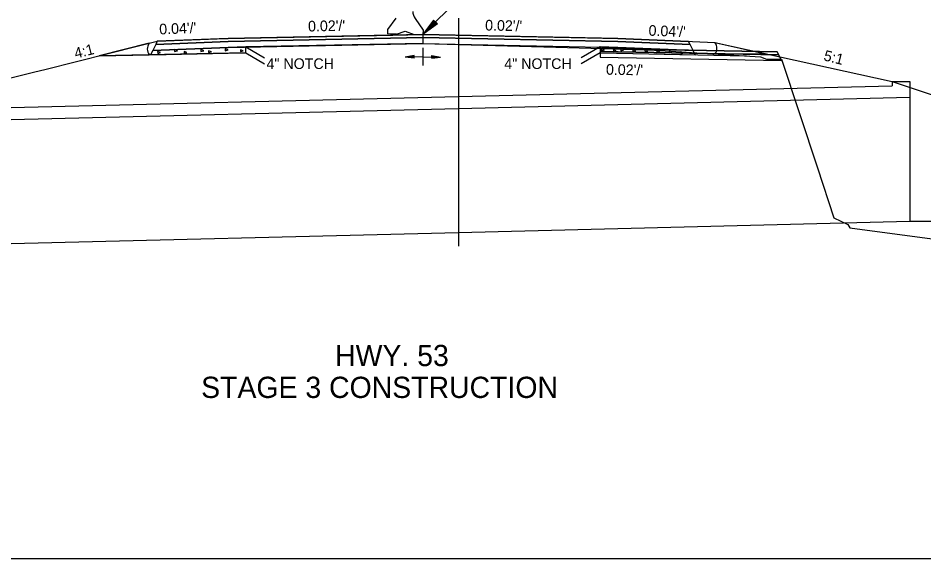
# Model space of a CAD drawing. Extents: x 2829243 to 2838161, y 467639 to 474695.
# Drawn here: x 2830142 to 2830653, y 468471 to 468777 of the extents above; entities that cross this region are included whole.
import ezdxf

# ---------------------------------------------------------------- set-up
doc = ezdxf.new("R2010")
doc.units = 0
for name, color, linetype in [('Default', 7, 'Continuous'), ('R_Dimension', 7, 'Continuous'), ('R_Draft', 7, 'Continuous'), ('R_Exist Surface', 7, 'Continuous'), ('R_Fin Surface', 7, 'Continuous'), ('R_MOT', 7, 'Continuous'), ('R_Water', 7, 'Continuous')]:
    doc.layers.add(name, color=color, linetype=linetype)

msp = doc.modelspace()

# ---------------------------------------------------------------- linework, layer by layer
at = {"layer": 'Default'}
msp.add_lwpolyline([(2829486.2, 470265.93), (2831121.84, 470265.93), (2831121.84, 468471.1), (2829486.2, 468471.1)], close=True, dxfattribs=at)
at = {"layer": 'R_Dimension'}
for p, q in [((2830370.56, 468767.33), (2830392.31, 468789.08)), ((2830376.57, 468775.47), (2830370.56, 468767.33)), ((2830376.75, 468775.29), (2830371.74, 468768.52)), ((2830378.52, 468773.52), (2830371.74, 468768.52)), ((2830376.93, 468775.11), (2830372.96, 468769.73)), ((2830378.34, 468773.7), (2830372.96, 468769.73)), ((2830377.11, 468774.93), (2830374.14, 468770.91)), ((2830378.16, 468773.88), (2830374.14, 468770.91)), ((2830377.29, 468774.75), (2830375.34, 468772.11)), ((2830377.98, 468774.06), (2830375.34, 468772.11)), ((2830377.47, 468774.57), (2830376.52, 468773.29)), ((2830377.8, 468774.24), (2830376.52, 468773.29)), ((2830378.7, 468773.35), (2830376.57, 468775.47)), ((2830378.7, 468773.35), (2830370.56, 468767.33)), ((2830220.56, 468763.53), (2830219.7, 468761.8)), ((2830219.7, 468761.8), (2830260.56, 468763.43)), ((2830260.56, 468763.43), (2830219.7, 468761.8)), ((2830260.56, 468765.13), (2830220.56, 468763.53)), ((2830370.56, 468767.33), (2830260.56, 468765.13)), ((2830260.56, 468763.43), (2830370.56, 468765.63)), ((2830370.56, 468765.63), (2830260.56, 468763.43)), ((2830370.56, 468767.33), (2830370.56, 468767.33)), ((2830370.56, 468767.33), (2830370.56, 468767.33)), ((2830480.56, 468765.13), (2830370.56, 468767.33)), ((2830370.56, 468767.33), (2830370.56, 468767.33)), ((2830370.56, 468767.33), (2830370.56, 468767.33)), ((2830370.56, 468767.33), (2830370.56, 468765.63)), ((2830370.56, 468765.63), (2830370.56, 468765.63)), ((2830370.56, 468765.63), (2830370.56, 468765.63)), ((2830370.56, 468765.63), (2830370.56, 468765.63)), ((2830370.56, 468765.63), (2830370.56, 468765.63)), ((2830370.56, 468765.63), (2830370.56, 468765.63)), ((2830370.56, 468765.63), (2830370.56, 468765.63)), ((2830370.56, 468765.63), (2830370.56, 468765.63)), ((2830370.56, 468765.63), (2830480.56, 468763.43)), ((2830480.56, 468763.43), (2830370.56, 468765.63)), ((2830370.56, 468765.63), (2830370.56, 468765.63)), ((2830370.56, 468765.63), (2830370.56, 468765.63)), ((2830370.56, 468765.63), (2830370.56, 468765.63)), ((2830520.58, 468763.49), (2830480.56, 468765.13)), ((2830480.56, 468763.43), (2830521.43, 468761.8)), ((2830521.43, 468761.8), (2830480.56, 468763.43)), ((2830521.43, 468761.8), (2830520.58, 468763.49)), ((2830216.04, 468762.4), (2830187.79, 468755.34)), ((2830218.01, 468758.43), (2830216.76, 468755.92)), ((2830219.7, 468761.8), (2830218.01, 468758.43)), ((2830218.01, 468758.43), (2830260.56, 468760.13)), ((2830260.56, 468760.13), (2830218.01, 468758.43)), ((2830260.56, 468760.13), (2830370.56, 468762.33)), ((2830370.56, 468762.33), (2830370.56, 468762.33)), ((2830370.56, 468762.33), (2830370.56, 468762.33)), ((2830370.56, 468762.33), (2830370.56, 468762.33)), ((2830370.56, 468762.33), (2830370.56, 468762.33)), ((2830370.56, 468762.33), (2830370.56, 468762.33)), ((2830370.56, 468762.33), (2830480.56, 468760.13)), ((2830370.56, 468759.79), (2830370.56, 468749.79)), ((2830370.56, 468759.79), (2830370.56, 468749.79)), ((2830570.61, 468757.53), (2830470.56, 468759.53)), ((2830470.56, 468759.53), (2830470.56, 468759.53)), ((2830470.56, 468759.53), (2830470.56, 468759.53)), ((2830470.56, 468759.53), (2830470.56, 468759.53)), ((2830470.56, 468759.53), (2830470.56, 468757.83)), ((2830480.56, 468760.13), (2830523.12, 468758.43)), ((2830523.12, 468758.42), (2830480.56, 468760.13)), ((2830523.12, 468758.43), (2830521.43, 468761.8)), ((2830524.35, 468755.96), (2830523.12, 468758.42)), ((2830535.45, 468762.79), (2830564.01, 468756.51)), ((2830187.79, 468755.34), (2830216.15, 468755.91)), ((2830216.76, 468755.92), (2830260.56, 468756.8)), ((2830365.55, 468755.44), (2830360.56, 468754.59)), ((2830365.55, 468755.44), (2830360.56, 468754.59)), ((2830370.56, 468754.79), (2830360.56, 468754.59)), ((2830370.56, 468754.79), (2830360.56, 468754.59)), ((2830365.58, 468753.94), (2830360.56, 468754.59)), ((2830365.58, 468753.94), (2830360.56, 468754.59)), ((2830365.55, 468755.32), (2830361.4, 468754.61)), ((2830365.55, 468755.32), (2830361.4, 468754.61)), ((2830365.58, 468754.07), (2830361.4, 468754.61)), ((2830365.58, 468754.07), (2830361.4, 468754.61)), ((2830365.55, 468755.19), (2830362.26, 468754.63)), ((2830365.55, 468755.19), (2830362.26, 468754.63)), ((2830365.57, 468754.2), (2830362.26, 468754.63)), ((2830365.57, 468754.2), (2830362.26, 468754.63)), ((2830365.56, 468755.07), (2830363.09, 468754.64)), ((2830365.56, 468755.07), (2830363.09, 468754.64)), ((2830365.57, 468754.32), (2830363.09, 468754.64)), ((2830365.57, 468754.32), (2830363.09, 468754.64)), ((2830365.56, 468754.94), (2830363.94, 468754.66)), ((2830365.56, 468754.94), (2830363.94, 468754.66)), ((2830365.57, 468754.45), (2830363.94, 468754.66)), ((2830365.57, 468754.45), (2830363.94, 468754.66)), ((2830365.56, 468754.81), (2830364.77, 468754.68)), ((2830365.56, 468754.81), (2830364.77, 468754.68)), ((2830365.57, 468754.58), (2830364.77, 468754.68)), ((2830365.57, 468754.58), (2830364.77, 468754.68)), ((2830365.58, 468753.94), (2830365.55, 468755.44)), ((2830365.58, 468753.94), (2830365.55, 468755.44)), ((2830370.56, 468754.79), (2830380.56, 468754.59)), ((2830370.56, 468754.79), (2830380.56, 468754.59)), ((2830375.55, 468753.94), (2830375.58, 468755.44)), ((2830375.55, 468753.94), (2830375.58, 468755.44)), ((2830375.55, 468754.07), (2830379.73, 468754.61)), ((2830375.55, 468754.07), (2830379.73, 468754.61)), ((2830375.55, 468753.94), (2830380.56, 468754.59)), ((2830375.55, 468753.94), (2830380.56, 468754.59)), ((2830375.56, 468754.58), (2830376.35, 468754.68)), ((2830375.56, 468754.58), (2830376.35, 468754.68)), ((2830375.56, 468754.45), (2830377.19, 468754.66)), ((2830375.56, 468754.45), (2830377.19, 468754.66)), ((2830375.56, 468754.32), (2830378.04, 468754.64)), ((2830375.56, 468754.32), (2830378.04, 468754.64)), ((2830375.56, 468754.2), (2830378.87, 468754.63)), ((2830375.56, 468754.2), (2830378.87, 468754.63)), ((2830375.57, 468755.19), (2830378.87, 468754.63)), ((2830375.57, 468755.19), (2830378.87, 468754.63)), ((2830375.57, 468755.07), (2830378.04, 468754.64)), ((2830375.57, 468755.07), (2830378.04, 468754.64)), ((2830375.57, 468754.94), (2830377.19, 468754.66)), ((2830375.57, 468754.94), (2830377.19, 468754.66)), ((2830375.57, 468754.81), (2830376.35, 468754.68)), ((2830375.57, 468754.81), (2830376.35, 468754.68)), ((2830375.58, 468755.44), (2830380.56, 468754.59)), ((2830375.58, 468755.44), (2830380.56, 468754.59)), ((2830375.58, 468755.32), (2830379.73, 468754.61)), ((2830375.58, 468755.32), (2830379.73, 468754.61)), ((2830470.56, 468757.83), (2830470.56, 468757.83)), ((2830470.56, 468757.83), (2830571.48, 468755.81)), ((2830571.48, 468755.81), (2830470.56, 468757.83)), ((2830470.56, 468757.83), (2830470.56, 468757.83)), ((2830470.56, 468757.83), (2830470.56, 468757.83)), ((2830470.56, 468757.83), (2830470.56, 468757.83)), ((2830470.56, 468757.83), (2830470.56, 468754.53)), ((2830470.56, 468754.53), (2830470.56, 468754.53)), ((2830470.56, 468754.53), (2830573.08, 468752.62)), ((2830480.56, 468756.8), (2830524.35, 468755.96)), ((2830564.01, 468756.51), (2830535.33, 468756.29)), ((2830570.61, 468757.53), (2830570.61, 468757.53)), ((2830571.48, 468755.81), (2830570.61, 468757.53)), ((2830570.61, 468757.53), (2830570.61, 468757.53)), ((2830573.08, 468752.62), (2830571.48, 468755.81)), ((2830571.48, 468755.81), (2830571.48, 468755.81)), ((2830571.48, 468755.81), (2830571.48, 468755.81))]:
    msp.add_line(p, q, dxfattribs=at)
for points in [[(2830260.56, 468756.8), (2830270.56, 468757), (2830270.56, 468760.33), (2830260.56, 468760.13)], [(2830480.56, 468760.13), (2830470.56, 468760.33), (2830470.56, 468757), (2830480.56, 468756.8)]]:
    msp.add_lwpolyline(points, dxfattribs=at)
for centre, start, end in [((2830219.95, 468759.22), 140.9001, 221.1293), ((2830531.54, 468759.61), 318.8707, 39.0999)]:
    msp.add_arc(centre, 5.04, start, end, dxfattribs=at)
at = {"layer": 'R_Draft'}
for p, q in [((2830390.56, 468776.59), (2830390.56, 468647.86)), ((2830370.56, 468767.33), (2830260.56, 468765.13)), ((2830370.56, 468765.63), (2830270.56, 468763.63)), ((2830370.56, 468767.33), (2830370.56, 468762.33)), ((2830480.56, 468765.13), (2830520.58, 468763.49)), ((2830480.56, 468763.43), (2830501.43, 468762.6)), ((2830370.56, 468762.33), (2830270.56, 468760.33)), ((2830270.56, 468760.33), (2830281.14, 468754.23)), ((2830470.56, 468760.33), (2830459.99, 468754.23)), ((2830470.56, 468760.33), (2830470.56, 468757)), ((2830480.56, 468760.13), (2830503.12, 468759.23)), ((2830270.56, 468757), (2830187.79, 468755.34)), ((2830270.56, 468757), (2830281.14, 468750.89)), ((2830470.56, 468757), (2830459.99, 468750.89)), ((2830470.56, 468757), (2830553.33, 468755.34))]:
    msp.add_line(p, q, dxfattribs=at)
for points in [[(2830231.92, 468758.25), (2830230.26, 468758.85), (2830230.31, 468757.75), (2830231.92, 468758.25)], [(2830246.81, 468758.25), (2830245.15, 468758.85), (2830245.2, 468757.75), (2830246.81, 468758.25)], [(2830251.1, 468757.63), (2830249.44, 468758.24), (2830249.49, 468757.14), (2830251.1, 468757.63)], [(2830260.58, 468758.7), (2830258.92, 468759.3), (2830258.97, 468758.2), (2830260.58, 468758.7)], [(2830269.15, 468758.19), (2830267.49, 468758.79), (2830267.53, 468757.69), (2830269.15, 468758.19)], [(2830473.03, 468758.69), (2830471.37, 468759.29), (2830471.41, 468758.19), (2830473.03, 468758.69)], [(2830479.75, 468758.09), (2830478.09, 468758.69), (2830478.13, 468757.59), (2830479.75, 468758.09)], [(2830483.99, 468758.69), (2830482.33, 468759.29), (2830482.38, 468758.19), (2830483.99, 468758.69)], [(2830490.71, 468758.09), (2830489.05, 468758.69), (2830489.1, 468757.59), (2830490.71, 468758.09)], [(2830497.59, 468758.14), (2830495.93, 468758.75), (2830495.97, 468757.65), (2830497.59, 468758.14)], [(2830504.31, 468757.54), (2830502.65, 468758.15), (2830502.69, 468757.05), (2830504.31, 468757.54)], [(2830511.18, 468757.6), (2830509.52, 468758.2), (2830509.57, 468757.1), (2830511.18, 468757.6)], [(2830222.44, 468757.18), (2830220.78, 468757.78), (2830220.83, 468756.68), (2830222.44, 468757.18)], [(2830237.33, 468757.18), (2830235.67, 468757.78), (2830235.72, 468756.68), (2830237.33, 468757.18)], [(2830517.9, 468756.99), (2830516.24, 468757.6), (2830516.29, 468756.5), (2830517.9, 468756.99)]]:
    msp.add_lwpolyline(points, dxfattribs=at)
at = {"layer": 'R_Exist Surface'}
msp.add_line((2830370.56, 468762.33), (2830270.56, 468760.33), dxfattribs=at)
msp.add_lwpolyline([(2830370.56, 468762.33), (2830445.65, 468760.26), (2830472.01, 468759.49), (2830501.37, 468758.49), (2830561.18, 468754.86), (2830564.55, 468753.49), (2830572.96, 468753.39), (2830593.41, 468692.09), (2830602.55, 468663.74), (2830610.47, 468660.13), (2830611.63, 468658.15), (2830752.48, 468639.25), (2830801.98, 468636.51), (2830819.56, 468636.66), (2830979.28, 468644.11), (2830991.76, 468643.84), (2831056.78, 468664.13), (2831065.2, 468667.65)], dxfattribs=at)
at = {"layer": 'R_Fin Surface'}
for p, q in [((2830470.56, 468759.53), (2830570.61, 468757.53)), ((2830570.61, 468757.53), (2830573.08, 468752.62))]:
    msp.add_line(p, q, dxfattribs=at)
for points in [[(2829665.37, 468586.85), (2830120.56, 468738.53), (2830151.43, 468746.25), (2830157.09, 468747.67), (2830210.73, 468761.08), (2830220.56, 468763.53), (2830254.37, 468764.89), (2830260.56, 468765.13), (2830353.52, 468766.99), (2830370.56, 468767.33)], [(2830370.56, 468767.33), (2830463.52, 468765.48), (2830480.56, 468765.13), (2830514.37, 468763.78), (2830535.45, 468762.79)], [(2830535.45, 468762.79), (2830635.45, 468740.8), (2830932.13, 468641.91)]]:
    msp.add_lwpolyline(points, dxfattribs=at)
at = {"layer": 'R_MOT'}
for p, q in [((2830355.35, 468776.71), (2830350.62, 468770.23)), ((2830366.15, 468776.49), (2830370.61, 468769.83)), ((2830350.62, 468770.23), (2830350.57, 468767.73)), ((2830355.57, 468767.63), (2830360.6, 468769.2)), ((2830360.6, 468769.2), (2830365.56, 468767.43)), ((2830370.61, 468769.83), (2830370.56, 468767.33)), ((2830355.57, 468767.63), (2830350.57, 468767.73)), ((2830365.56, 468767.43), (2830370.56, 468767.33))]:
    msp.add_line(p, q, dxfattribs=at)
msp.add_arc((2830373.07, 468781.14), 8.33, 184.8632, 213.8462, dxfattribs=at)
at = {"layer": 'R_Water'}
for p, q in [((2830390.56, 468732.29), (2830635.45, 468738.34)), ((2830635.45, 468740.8), (2830645.45, 468740.8)), ((2830635.45, 468740.8), (2830635.45, 468738.34)), ((2830645.45, 468740.8), (2830645.45, 468661.56)), ((2830078, 468724.59), (2830390.56, 468732.29)), ((2830390.56, 468725.59), (2830645.45, 468731.89)), ((2830068, 468717.63), (2830390.56, 468725.59)), ((2830390.56, 468655.57), (2830645.46, 468661.86)), ((2830645.45, 468661.86), (2830872.27, 468661.86)), ((2830068, 468647.6), (2830390.56, 468655.57))]:
    msp.add_line(p, q, dxfattribs=at)

# ---------------------------------------------------------------- texts
at = {"layer": 'R_Dimension'}
for s, rotation, p in [("0.04'/'", 2.2906, (2830221.78, 468767.4)), ("0.02'/'", 1.1458, (2830305.75, 468769.08)), ("0.02'/'", 358.8542, (2830405.63, 468769.68)), ("0.04'/'", 357.7094, (2830497.86, 468766.76)), ('4:1', 14.036, (2830174.53, 468753.74)), ('5:1', 345.964, (2830596.43, 468752.86)), ("0.02'/'", 358.8542, (2830473.85, 468744.7))]:
    msp.add_text(s, height=6, rotation=rotation, dxfattribs=at).set_placement(p)
for p in [(2830282.25, 468747.9), (2830416.5, 468747.9)]:
    msp.add_text('4" NOTCH', height=6, dxfattribs=at).set_placement(p)
at = {"layer": 'R_Draft'}
for s, p in [('HWY. 53', (2830320.97, 468580.03)), ('STAGE 3 CONSTRUCTION', (2830245.33, 468562.03))]:
    msp.add_text(s, height=12, dxfattribs=at).set_placement(p)
at = {"layer": 'R_MOT'}
msp.add_text('DWB 1-14-10', height=0.04, rotation=88.8542, dxfattribs=at).set_placement((2830350.64, 468767.8))

doc.saveas('drawing.dxf')
